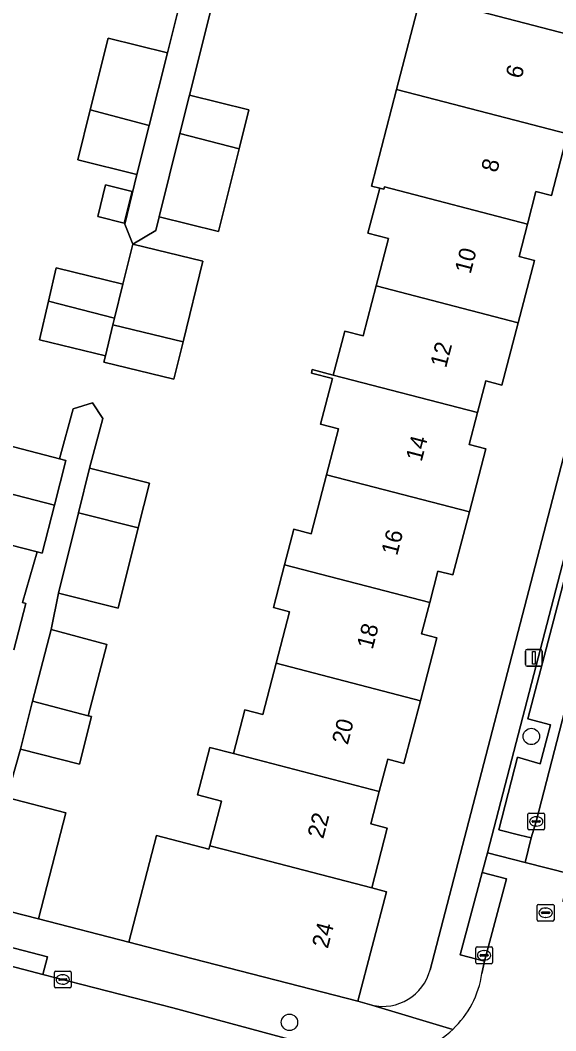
# Model space of a CAD drawing. Extents: x 163683 to 164494, y 382709 to 383872.
# Drawn here: x 164008.9 to 164040.9, y 383166.6 to 383227 of the extents above; entities that cross this region are included whole.
import ezdxf

# ---------------------------------------------------------------- set-up
doc = ezdxf.new("R2010")
doc.units = 0
for name, color, linetype in [('IMGEO_Boom', 7, 'Continuous'), ('IMGEO_Erf', 7, 'Continuous'), ('IMGEO_Groenvoorziening', 7, 'Continuous'), ('IMGEO_Kolk', 7, 'Continuous'), ('IMGEO_Lichtmast', 7, 'Continuous'), ('IMGEO_Muur', 7, 'Continuous'), ('IMGEO_Pand', 7, 'Continuous'), ('IMGEO_Pand_nummerreeks', 7, 'Continuous'), ('IMGEO_Parkeervlak_halfverhard', 7, 'Continuous'), ('IMGEO_Rijbaan_lokaal_open', 7, 'Continuous'), ('IMGEO_Rioolput', 7, 'Continuous'), ('IMGEO_Voetpad_open', 7, 'Continuous')]:
    doc.layers.add(name, color=color, linetype=linetype)

msp = doc.modelspace()

# ---------------------------------------------------------------- linework, layer by layer
at = {"layer": 'IMGEO_Boom'}
for centre in [(164039.461, 383184.161), (164025.018, 383167.075)]:
    msp.add_circle(centre, 0.489, dxfattribs=at)
at = {"layer": 'IMGEO_Erf'}
for points in [[(164033.418, 383170.22), (164049.31, 383231.356)], [(164008.168, 383201.569), (164011.284, 383200.761), (164012.097, 383203.735), (164013.259, 383204.092), (164013.872, 383203.166), (164013.083, 383200.19), (164016.653, 383199.3), (164015.988, 383196.632), (164014.79, 383191.829), (164011.22, 383192.719), (164010.792, 383190.558), (164014.117, 383189.662), (164012.999, 383185.397), (164013.193, 383185.346), (164012.487, 383182.513), (164008.951, 383183.394), (164008.145, 383180.506), (164011.664, 383179.6), (164010.032, 383173.256), (164015.42, 383171.857), (164017.069, 383178.241), (164020.212, 383177.429), (164020.261, 383177.617), (164020.953, 383180.296), (164019.526, 383180.668), (164020.264, 383183.505), (164021.678, 383183.137), (164022.36, 383185.757), (164023.432, 383185.478), (164024.229, 383188.54), (164025.027, 383191.609), (164024.063, 383191.86), (164024.729, 383194.418), (164025.282, 383196.543), (164026.305, 383196.276), (164027.223, 383199.805), (164027.937, 383202.547), (164026.868, 383202.825), (164027.579, 383205.556), (164026.325, 383205.882), (164026.378, 383206.085), (164027.632, 383205.759), (164028.317, 383208.391), (164029.415, 383208.105), (164030.193, 383211.097), (164030.927, 383213.916), (164029.707, 383214.234), (164030.409, 383216.927), (164029.918, 383217.054), (164031.418, 383222.826), (164032.872, 383228.418)], [(164020.518, 383228.388), (164019.05, 383222.496), (164022.586, 383221.614), (164022.006, 383219.287), (164020.772, 383214.333), (164017.236, 383215.215), (164017.032, 383214.396), (164015.656, 383213.584), (164015.191, 383214.79), (164015.913, 383217.744), (164012.376, 383218.626), (164013.119, 383221.604), (164014.191, 383225.906), (164017.727, 383225.025), (164018.442, 383227.897)], [(164041.621, 383220.172), (164040.663, 383216.49), (164039.738, 383216.73), (164039.233, 383214.788), (164038.727, 383212.845), (164039.643, 383212.606), (164038.675, 383208.885), (164037.707, 383205.167), (164036.74, 383205.418), (164036.245, 383203.518), (164035.75, 383201.614), (164036.746, 383201.355), (164035.764, 383197.585), (164034.783, 383193.815), (164033.886, 383194.049), (164033.397, 383192.17), (164032.908, 383190.289), (164033.812, 383190.054), (164032.834, 383186.299), (164031.857, 383182.545), (164030.885, 383182.798), (164030.383, 383180.87), (164029.881, 383178.941), (164030.861, 383178.686), (164029.93, 383175.11), (164030.804, 383174.882), (164029.1, 383168.333), (164029.927, 383168.105)], [(164008.549, 383189.346), (164009.275, 383192.116), (164009.071, 383192.17), (164009.943, 383195.195), (164006.756, 383196.021)]]:
    msp.add_lwpolyline(points, dxfattribs=at)
for points in [[(164013.571, 383215.234), (164014.042, 383217.125), (164015.618, 383216.732), (164015.146, 383214.841)], [(164015.656, 383213.584), (164019.843, 383212.56), (164018.665, 383207.739), (164018.121, 383205.515), (164013.934, 383206.538), (164014.024, 383206.906), (164010.085, 383207.869), (164010.629, 383210.182), (164011.095, 383212.168), (164015.073, 383211.196)]]:
    msp.add_lwpolyline(points, close=True, dxfattribs=at)
msp.add_arc((164030.589, 383170.951), 2.922, 256.91087, 345.50775, dxfattribs=at)
at = {"layer": 'IMGEO_Groenvoorziening'}
msp.add_lwpolyline([(164049.582, 383226.272), (164036.847, 383177.21), (164038.313, 383176.836), (164039.101, 383176.635), (164039.458, 383178.102), (164038.777, 383178.268), (164037.521, 383178.575), (164038.64, 383182.922), (164039.987, 383182.527), (164040.604, 383184.852), (164039.255, 383185.208), (164041.785, 383194.874)], dxfattribs=at)
at = {"layer": 'IMGEO_Kolk'}
for p, q in [((164039.254, 383178.658), (164039.254, 383179.51)), ((164039.329, 383179.584), (164040.181, 383179.584)), ((164040.255, 383179.51), (164040.255, 383178.658)), ((164039.513, 383179.078), (164039.513, 383179.09)), ((164039.951, 383179.041), (164039.553, 383179.041)), ((164039.556, 383179.127), (164039.954, 383179.127)), ((164039.742, 383179.364), (164039.767, 383179.364)), ((164039.997, 383179.09), (164039.997, 383179.078)), ((164040.181, 383178.584), (164039.329, 383178.584)), ((164039.765, 383178.804), (164039.74, 383178.804)), ((164036.217, 383171.581), (164037.069, 383171.581)), ((164036.142, 383170.655), (164036.142, 383171.507)), ((164036.401, 383171.075), (164036.401, 383171.087)), ((164036.839, 383171.038), (164036.441, 383171.038)), ((164036.444, 383171.124), (164036.842, 383171.124)), ((164036.63, 383171.361), (164036.655, 383171.361)), ((164036.885, 383171.087), (164036.885, 383171.075)), ((164037.143, 383171.507), (164037.143, 383170.655)), ((164037.069, 383170.581), (164036.217, 383170.581)), ((164036.653, 383170.801), (164036.628, 383170.801)), ((164010.977, 383169.21), (164010.977, 383170.062)), ((164011.052, 383170.136), (164011.904, 383170.136)), ((164011.465, 383169.916), (164011.49, 383169.916)), ((164011.978, 383170.062), (164011.978, 383169.21)), ((164011.236, 383169.63), (164011.236, 383169.642)), ((164011.674, 383169.593), (164011.276, 383169.593)), ((164011.279, 383169.679), (164011.677, 383169.679)), ((164011.488, 383169.356), (164011.463, 383169.356)), ((164011.72, 383169.642), (164011.72, 383169.63)), ((164011.904, 383169.136), (164011.052, 383169.136))]:
    msp.add_line(p, q, dxfattribs=at)
for points in [[(164039.254, 383178.658), (164039.254, 383179.51)], [(164039.329, 383179.584), (164040.181, 383179.584)], [(164040.255, 383179.51), (164040.255, 383178.658)], [(164040.181, 383178.584), (164039.329, 383178.584)], [(164036.217, 383171.581), (164037.069, 383171.581)], [(164036.142, 383170.655), (164036.142, 383171.507)], [(164037.143, 383171.507), (164037.143, 383170.655)], [(164037.069, 383170.581), (164036.217, 383170.581)], [(164010.977, 383169.21), (164010.977, 383170.062)], [(164011.052, 383170.136), (164011.904, 383170.136)], [(164011.978, 383170.062), (164011.978, 383169.21)], [(164011.904, 383169.136), (164011.052, 383169.136)]]:
    msp.add_lwpolyline(points, dxfattribs=at)
for centre, radius, start, end in [((164039.331, 383179.508), 0.0765, 91.55205, 178.44795), ((164039.331, 383179.508), 0.0765, 91.55205, 178.44795), ((164040.179, 383179.508), 0.0765, 1.55205, 88.44795), ((164040.179, 383179.508), 0.0765, 1.55205, 88.44795), ((164039.553, 383179.087), 0.0403, 85.87752, 175.75265), ((164039.55, 383179.077), 0.0366, 178.93798, 274.71019), ((164039.954, 383179.084), 0.043, 264.86636, 352.45326), ((164039.958, 383179.089), 0.0386, 1.73085, 96.63898), ((164039.331, 383178.66), 0.0765, 181.55205, 268.44795), ((164039.331, 383178.66), 0.0765, 181.55205, 268.44795), ((164040.179, 383178.66), 0.0765, 271.55205, 358.44795), ((164040.179, 383178.66), 0.0765, 271.55205, 358.44795), ((164036.219, 383171.505), 0.0765, 91.55205, 178.44795), ((164036.219, 383171.505), 0.0765, 91.55205, 178.44795), ((164037.067, 383171.505), 0.0765, 1.55205, 88.44795), ((164037.067, 383171.505), 0.0765, 1.55205, 88.44795), ((164036.441, 383171.084), 0.0403, 85.87752, 175.75265), ((164036.438, 383171.074), 0.0366, 178.93798, 274.71019), ((164036.842, 383171.081), 0.043, 264.86636, 352.45326), ((164036.846, 383171.086), 0.0386, 1.73085, 96.63898), ((164036.219, 383170.657), 0.0765, 181.55205, 268.44795), ((164036.219, 383170.657), 0.0765, 181.55205, 268.44795), ((164037.067, 383170.657), 0.0765, 271.55205, 358.44795), ((164037.067, 383170.657), 0.0765, 271.55205, 358.44795), ((164011.054, 383170.06), 0.0765, 91.55205, 178.44795), ((164011.054, 383170.06), 0.0765, 91.55205, 178.44795), ((164011.902, 383170.06), 0.0765, 1.55205, 88.44795), ((164011.902, 383170.06), 0.0765, 1.55205, 88.44795), ((164011.054, 383169.212), 0.0765, 181.55205, 268.44795), ((164011.054, 383169.212), 0.0765, 181.55205, 268.44795), ((164011.276, 383169.639), 0.0403, 85.87752, 175.75265), ((164011.273, 383169.629), 0.0366, 178.93798, 274.71019), ((164011.677, 383169.636), 0.043, 264.86636, 352.45326), ((164011.681, 383169.641), 0.0386, 1.73085, 96.63898), ((164011.902, 383169.212), 0.0765, 271.55205, 358.44795), ((164011.902, 383169.212), 0.0765, 271.55205, 358.44795)]:
    msp.add_arc(centre, radius, start, end, dxfattribs=at)
for centre, major_axis, ratio, start_param, end_param in [((164039.741, 383179.084), (-0.387, 0.002), 0.722429, 4.712389, 7.853982), ((164039.766, 383179.084), (-0.39, 0.002), 0.717154, 1.570796, 4.712389), ((164036.629, 383171.081), (-0.387, 0.002), 0.722429, 4.712389, 7.853982), ((164036.654, 383171.081), (-0.39, 0.002), 0.717154, 1.570796, 4.712389), ((164011.464, 383169.636), (-0.387, 0.002), 0.722429, 4.712389, 7.853982), ((164011.489, 383169.636), (-0.39, 0.002), 0.717154, 1.570796, 4.712389)]:
    msp.add_ellipse(centre, major_axis=major_axis, ratio=ratio, start_param=start_param, end_param=end_param, dxfattribs=at)
at = {"layer": 'IMGEO_Lichtmast'}
for p, q in [((164039.112, 383188.46), (164039.112, 383189.26)), ((164039.112, 383189.26), (164039.112, 383188.46)), ((164039.212, 383189.36), (164040.002, 383189.36)), ((164040.002, 383189.36), (164039.212, 383189.36)), ((164040.102, 383189.26), (164040.102, 383188.46)), ((164040.102, 383188.46), (164040.102, 383189.26)), ((164040.002, 383188.36), (164039.212, 383188.36)), ((164039.212, 383188.36), (164040.002, 383188.36))]:
    msp.add_line(p, q, dxfattribs=at)
msp.add_lwpolyline([(164039.532, 383189.235), (164039.682, 383189.235), (164039.682, 383188.485), (164039.532, 383188.485), (164039.532, 383189.235)], dxfattribs=at)
for centre, start, end in [((164039.212, 383189.26), 90, 180), ((164039.212, 383189.26), 90, 180), ((164040.002, 383189.26), 0, 90), ((164040.002, 383189.26), 360, 90), ((164039.212, 383188.46), 180, 270), ((164039.212, 383188.46), 180, 270), ((164040.002, 383188.46), 270, 0), ((164040.002, 383188.46), 270, 0)]:
    msp.add_arc(centre, 0.1, start, end, dxfattribs=at)
at = {"layer": 'IMGEO_Muur'}
msp.add_lwpolyline([(164018.564, 383171.047), (164010.032, 383173.256)], dxfattribs=at)
at = {"layer": 'IMGEO_Pand'}
for points in [[(164044.515, 383231.23), (164036.123, 383233.411), (164035.417, 383230.701), (164033.278, 383231.258), (164032.56, 383228.499), (164032.872, 383228.418), (164042.145, 383225.998), (164042.639, 383227.894), (164043.583, 383227.648)], [(164042.145, 383225.998), (164032.872, 383228.418), (164031.418, 383222.826), (164033.183, 383222.367), (164041.621, 383220.172), (164042.58, 383223.857), (164041.651, 383224.099)], [(164016.645, 383220.683), (164017.727, 383225.025), (164014.191, 383225.906), (164013.119, 383221.604)], [(164018.48, 383220.208), (164022.006, 383219.287), (164022.586, 383221.614), (164019.05, 383222.496)], [(164041.621, 383220.172), (164033.183, 383222.367), (164031.418, 383222.826), (164029.918, 383217.054), (164030.409, 383216.927), (164030.647, 383216.865), (164030.687, 383217.02), (164039.233, 383214.788), (164039.738, 383216.73), (164040.663, 383216.49)], [(164016.645, 383220.683), (164013.119, 383221.604), (164012.376, 383218.626), (164015.913, 383217.744)], [(164018.48, 383220.208), (164017.236, 383215.215), (164020.772, 383214.333), (164022.006, 383219.287)], [(164015.618, 383216.732), (164014.042, 383217.125), (164013.571, 383215.234), (164015.146, 383214.841)], [(164039.233, 383214.788), (164030.687, 383217.02), (164030.647, 383216.865), (164030.409, 383216.927), (164029.707, 383214.234), (164030.927, 383213.916), (164030.193, 383211.097), (164038.675, 383208.885), (164039.643, 383212.606), (164038.727, 383212.845)], [(164015.656, 383213.584), (164015.073, 383211.196), (164014.574, 383209.156), (164014.478, 383208.762), (164018.665, 383207.739), (164019.843, 383212.56)], [(164015.073, 383211.196), (164011.095, 383212.168), (164010.629, 383210.182), (164014.574, 383209.156)], [(164038.675, 383208.885), (164030.193, 383211.097), (164029.415, 383208.105), (164028.317, 383208.391), (164027.632, 383205.759), (164036.245, 383203.518), (164036.74, 383205.418), (164037.707, 383205.167)], [(164014.478, 383208.762), (164014.574, 383209.156), (164010.629, 383210.182), (164010.085, 383207.869), (164014.024, 383206.906)], [(164018.665, 383207.739), (164014.478, 383208.762), (164014.024, 383206.906), (164013.934, 383206.538), (164018.121, 383205.515)], [(164036.245, 383203.518), (164027.632, 383205.759), (164026.378, 383206.085), (164026.325, 383205.882), (164027.579, 383205.556), (164026.868, 383202.825), (164027.937, 383202.547), (164027.223, 383199.805), (164035.764, 383197.585), (164036.746, 383201.355), (164035.75, 383201.614)], [(164011.284, 383200.761), (164008.168, 383201.569), (164007.507, 383198.884), (164010.993, 383197.981), (164011.662, 383200.663)], [(164013.083, 383200.19), (164012.418, 383197.523), (164015.988, 383196.632), (164016.653, 383199.3)], [(164027.223, 383199.805), (164026.305, 383196.276), (164025.282, 383196.543), (164024.729, 383194.418), (164033.397, 383192.17), (164033.886, 383194.049), (164034.783, 383193.815), (164035.764, 383197.585)], [(164010.993, 383197.981), (164007.507, 383198.884), (164006.756, 383196.021), (164009.943, 383195.195), (164010.251, 383195.115)], [(164015.988, 383196.632), (164012.418, 383197.523), (164011.22, 383192.719), (164014.79, 383191.829)], [(164032.834, 383186.299), (164033.812, 383190.054), (164032.908, 383190.289), (164033.397, 383192.17), (164024.729, 383194.418), (164024.063, 383191.86), (164025.027, 383191.609), (164024.229, 383188.54)], [(164014.117, 383189.662), (164010.792, 383190.558), (164009.666, 383186.265), (164012.999, 383185.397)], [(164032.834, 383186.299), (164024.229, 383188.54), (164023.432, 383185.478), (164022.36, 383185.757), (164021.678, 383183.137), (164030.383, 383180.87), (164030.885, 383182.798), (164031.857, 383182.545)], [(164013.193, 383185.346), (164012.999, 383185.397), (164009.666, 383186.265), (164008.951, 383183.394), (164012.487, 383182.513)], [(164030.383, 383180.87), (164021.678, 383183.137), (164020.264, 383183.505), (164019.526, 383180.668), (164020.953, 383180.296), (164020.261, 383177.617), (164021.819, 383177.222), (164029.93, 383175.11), (164030.861, 383178.686), (164029.881, 383178.941)], [(164010.032, 383173.256), (164011.664, 383179.6), (164008.145, 383180.506), (164006.512, 383174.162)], [(164030.804, 383174.882), (164029.93, 383175.11), (164021.819, 383177.222), (164020.261, 383177.617), (164020.212, 383177.429), (164017.069, 383178.241), (164015.42, 383171.857), (164018.564, 383171.047), (164029.1, 383168.333)]]:
    msp.add_lwpolyline(points, close=True, dxfattribs=at)
at = {"layer": 'IMGEO_Parkeervlak_halfverhard'}
msp.add_lwpolyline([(164041.785, 383194.874), (164039.255, 383185.208), (164040.604, 383184.852), (164039.987, 383182.527), (164038.64, 383182.922), (164037.521, 383178.575), (164038.777, 383178.268), (164039.458, 383178.102), (164039.755, 383179.084), (164043.016, 383191.738)], dxfattribs=at)
at = {"layer": 'IMGEO_Rijbaan_lokaal_open'}
for points in [[(164056.397, 383227.867), (164056.79, 383229.198), (164052.985, 383230.229), (164052.447, 383228.114), (164048.552, 383213.098), (164043.016, 383191.738), (164039.755, 383179.084), (164039.458, 383178.102), (164039.101, 383176.635), (164041.756, 383175.957), (164041.339, 383174.306)], [(164027.998, 383165.259), (164018.045, 383167.938), (164010.299, 383169.93), (163999.658, 383172.724), (163978.831, 383178.147)], [(164041.339, 383174.306), (164041.756, 383175.957), (164039.101, 383176.635), (164038.313, 383176.836), (164036.847, 383177.21), (164036.53, 383176.035), (164037.987, 383175.646), (164036.66, 383170.733), (164036.513, 383169.992)]]:
    msp.add_lwpolyline(points, dxfattribs=at)
for centre, radius, start, end in [((164030.874, 383170.816), 5.699, 313.06171, 351.68737), ((164030.881, 383170.808), 5.689, 274.36827, 313.06282)]:
    msp.add_arc(centre, radius, start, end, dxfattribs=at)
at = {"layer": 'IMGEO_Rioolput'}
for p, q in [((164039.814, 383173.201), (164039.814, 383174.053)), ((164039.889, 383174.127), (164040.741, 383174.127)), ((164040.815, 383174.053), (164040.815, 383173.201)), ((164040.073, 383173.621), (164040.073, 383173.633)), ((164040.511, 383173.584), (164040.113, 383173.584)), ((164040.116, 383173.67), (164040.514, 383173.67)), ((164040.302, 383173.907), (164040.327, 383173.907)), ((164040.557, 383173.633), (164040.557, 383173.621)), ((164040.741, 383173.127), (164039.889, 383173.127)), ((164040.325, 383173.347), (164040.3, 383173.347))]:
    msp.add_line(p, q, dxfattribs=at)
for points in [[(164039.814, 383173.201), (164039.814, 383174.053)], [(164039.889, 383174.127), (164040.741, 383174.127)], [(164040.815, 383174.053), (164040.815, 383173.201)], [(164040.741, 383173.127), (164039.889, 383173.127)]]:
    msp.add_lwpolyline(points, dxfattribs=at)
for centre, radius, start, end in [((164039.891, 383174.051), 0.0765, 91.55205, 178.44795), ((164039.891, 383174.051), 0.0765, 91.55205, 178.44795), ((164040.739, 383174.051), 0.0765, 1.55205, 88.44795), ((164040.739, 383174.051), 0.0765, 1.55205, 88.44795), ((164040.113, 383173.63), 0.0403, 85.87752, 175.75265), ((164040.11, 383173.62), 0.0366, 178.93798, 274.71019), ((164040.514, 383173.627), 0.043, 264.86636, 352.45326), ((164040.518, 383173.632), 0.0386, 1.73085, 96.63898), ((164039.891, 383173.203), 0.0765, 181.55205, 268.44795), ((164039.891, 383173.203), 0.0765, 181.55205, 268.44795), ((164040.739, 383173.203), 0.0765, 271.55205, 358.44795), ((164040.739, 383173.203), 0.0765, 271.55205, 358.44795)]:
    msp.add_arc(centre, radius, start, end, dxfattribs=at)
for centre, major_axis, ratio, start_param, end_param in [((164040.301, 383173.627), (-0.387, 0.002), 0.722429, 4.712389, 7.853982), ((164040.326, 383173.627), (-0.39, 0.002), 0.717154, 1.570796, 4.712389)]:
    msp.add_ellipse(centre, major_axis=major_axis, ratio=ratio, start_param=start_param, end_param=end_param, dxfattribs=at)
at = {"layer": 'IMGEO_Voetpad_open'}
for points in [[(164057.206, 383261.733), (164056.106, 383257.501), (164052.353, 383243.064), (164051.151, 383238.437), (164050.683, 383236.637), (164049.31, 383231.356), (164033.418, 383170.22)], [(164018.442, 383227.897), (164017.727, 383225.025), (164016.645, 383220.683), (164015.913, 383217.744), (164015.191, 383214.79), (164015.656, 383213.584), (164017.032, 383214.396), (164017.236, 383215.215), (164018.48, 383220.208), (164019.05, 383222.496), (164020.518, 383228.388)], [(164036.513, 383169.992), (164036.66, 383170.733), (164035.206, 383171.118), (164036.53, 383176.035), (164036.847, 383177.21), (164049.582, 383226.272)], [(164008.145, 383180.506), (164008.951, 383183.394), (164009.666, 383186.265), (164010.792, 383190.558), (164011.22, 383192.719), (164012.418, 383197.523), (164013.083, 383200.19), (164013.872, 383203.166), (164013.259, 383204.092), (164012.097, 383203.735), (164011.284, 383200.761), (164011.662, 383200.663), (164010.993, 383197.981), (164010.251, 383195.115), (164009.943, 383195.195), (164009.071, 383192.17), (164009.275, 383192.116), (164008.549, 383189.346)], [(163978.831, 383178.147), (163999.658, 383172.724), (163999.921, 383173.765), (164010.567, 383170.992), (164010.299, 383169.93), (164018.045, 383167.938), (164027.998, 383165.259)], [(164034.765, 383166.652), (164029.927, 383168.105), (164029.1, 383168.333), (164018.564, 383171.047), (164015.42, 383171.857), (164010.032, 383173.256), (164006.512, 383174.162)], [(164029.927, 383168.105), (164034.765, 383166.652)]]:
    msp.add_lwpolyline(points, dxfattribs=at)
for points in [[(164036.53, 383176.035), (164035.206, 383171.118), (164036.66, 383170.733), (164037.987, 383175.646)], [(164010.299, 383169.93), (164010.567, 383170.992), (163999.921, 383173.765), (163999.658, 383172.724)]]:
    msp.add_lwpolyline(points, close=True, dxfattribs=at)
for centre, radius, start, end in [((164030.589, 383170.951), 2.922, 256.91087, 345.50775), ((164030.874, 383170.816), 5.699, 313.06171, 351.68737), ((164030.881, 383170.808), 5.689, 274.36827, 313.06282)]:
    msp.add_arc(centre, radius, start, end, dxfattribs=at)

# ---------------------------------------------------------------- texts
at = {"layer": 'IMGEO_Pand_nummerreeks'}
for s, rotation, p in [('6', 75.39552, (164038.87, 383223.428)), ('8', 75.39552, (164037.409, 383217.821)), ('10', 75.39552, (164035.831, 383211.764)), ('12', 75.39552, (164034.368, 383206.147)), ('14', 75.39552, (164032.906, 383200.539)), ('16', 75.39466, (164031.444, 383194.928)), ('18', 75.39466, (164029.982, 383189.32)), ('20', 75.39552, (164028.497, 383183.621)), ('22', 75.39552, (164027.034, 383178.004)), ('24', 75.4127, (164027.305, 383171.443))]:
    msp.add_text(s, height=1, rotation=rotation, dxfattribs=at).set_placement(p)

doc.saveas('drawing.dxf')
